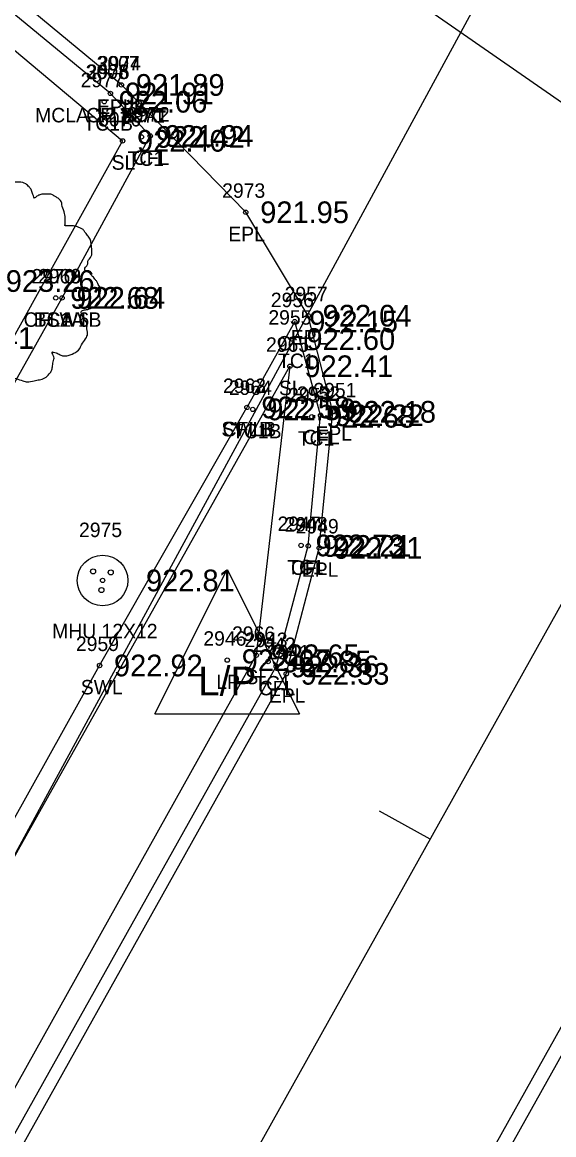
# Model space of a CAD drawing. Extents: x 1575382 to 1578175, y 1099175 to 1101955.
# Drawn here: x 1577037.7 to 1577074.4, y 1100704 to 1100781 of the extents above; entities that cross this region are included whole.
import ezdxf

# ---------------------------------------------------------------- set-up
doc = ezdxf.new("R2010")
doc.units = 0
for name, color, linetype in [('RD_EX_Conc', 7, 'Continuous'), ('RD_EX_Conc_txCode', 7, 'Continuous'), ('RD_EX_DR_Inlet', 7, 'Continuous'), ('RD_EX_Road', 7, 'Continuous'), ('RD_EX_Road_txCode', 7, 'Continuous'), ('RD_EX_TX_Conc_ELEV', 7, 'Continuous'), ('RD_EX_TX_Road_ELEV', 7, 'Continuous'), ('RD_EX_TX_UT_ELEV', 7, 'Continuous'), ('RD_EX_TX_VEG_ELEV', 7, 'Continuous'), ('RD_EX_UT', 7, 'Continuous'), ('RD_EX_UT_txCode', 7, 'Continuous'), ('RD_EX_VEG', 7, 'Continuous'), ('RD_EX_VEG_txCode', 7, 'Continuous'), ('RD_HC_Cl', 7, 'Continuous'), ('RD_HC_Data_Tic', 7, 'Continuous'), ('RD_SMD_Locator', 7, 'Continuous')]:
    doc.layers.add(name, color=color, linetype=linetype)

msp = doc.modelspace()

# ---------------------------------------------------------------- linework, layer by layer
at = {"layer": 'RD_EX_Conc'}
msp.add_line((1577028.227, 1100740.206), (1577040.428, 1100761.953), dxfattribs=at)
for points in [[(1577043.777, 1100776.098), (1576999.879, 1100812.296), (1576959.091, 1100842.628), (1576920.948, 1100878.726), (1576886.666, 1100919.361), (1576858.724, 1100961.136), (1576834.43, 1101008.647), (1576816.373, 1101055.231), (1576803.494, 1101104.71), (1576791.52, 1101152.573)], [(1577047.472, 1100660.341), (1577079.611, 1100717.857), (1577079.611, 1100717.857), (1577102.318, 1100758.516), (1577114.185, 1100779.635), (1577126.083, 1100804.335)], [(1577040.428, 1100761.953), (1577046.526, 1100773.156), (1577043.777, 1100776.098)], [(1576915.514, 1100485.425), (1576931.673, 1100514.72), (1576963.555, 1100571.695), (1576980.254, 1100601.726), (1577004.865, 1100645.934), (1577028.803, 1100689.209), (1577055.236, 1100736.453), (1577057.454, 1100744.788), (1577058.3, 1100753.828), (1577056.519, 1100760.313), (1577053.211, 1100754.373)], [(1576891.145, 1100492.999), (1576919.807, 1100523.916), (1576927.444, 1100533.738), (1576954.888, 1100579.32), (1576970.585, 1100607.096), (1576994.857, 1100650.35), (1577020.046, 1100695.255), (1577043.021, 1100736.517), (1577053.211, 1100754.373)]]:
    msp.add_lwpolyline(points, dxfattribs=at)
at = {"layer": 'RD_EX_DR_Inlet'}
for centre, radius in [((1577043.236, 1100742.401), 1.75), ((1577042.572, 1100743.031), 0.175), ((1577043.796, 1100742.961), 0.175), ((1577043.149, 1100741.737), 0.175)]:
    msp.add_circle(centre, radius, dxfattribs=at)
at = {"layer": 'RD_EX_Road'}
for points in [[(1576898.125, 1100449.597), (1576900.298, 1100453.323), (1576908.44, 1100470.191), (1576911.626, 1100476.811), (1576915.143, 1100482.86), (1576932.491, 1100514.031), (1576964.319, 1100571.231), (1576981.085, 1100601.291), (1577005.143, 1100644.548), (1577029.514, 1100688.699), (1577055.929, 1100735.941), (1577058.213, 1100744.654), (1577059.154, 1100754.07), (1577057.45, 1100760.722), (1577053.131, 1100767.877), (1577044.533, 1100776.687), (1577044.533, 1100776.687), (1577000.541, 1100813.123), (1576959.676, 1100843.401), (1576921.642, 1100879.474), (1576887.689, 1100919.798), (1576859.542, 1100961.835), (1576835.397, 1101008.919), (1576817.257, 1101055.711)], [(1576918.426, 1100436.45), (1576919.689, 1100438.104), (1576919.205, 1100438.447), (1576924.616, 1100446.412), (1576935.148, 1100461.397), (1576954.407, 1100495.424), (1576968.796, 1100521.524), (1576985.916, 1100552.3), (1577005.625, 1100587.417), (1577028.135, 1100627.58), (1577046.667, 1100660.868), (1577078.765, 1100718.331)]]:
    msp.add_lwpolyline(points, dxfattribs=at)
at = {"layer": 'RD_EX_UT'}
for p, q in [((1577046.854, 1100733.163), (1577051.854, 1100743.163)), ((1577051.854, 1100743.163), (1577056.854, 1100733.163)), ((1577046.854, 1100733.163), (1577056.854, 1100733.163))]:
    msp.add_line(p, q, dxfattribs=at)
msp.add_lwpolyline([(1576697.982, 1101074.318), (1577079.486, 1100801.524), (1576931.929, 1100529.296), (1577183.503, 1100413.666)], dxfattribs=at)
at = {"layer": 'RD_EX_VEG'}
for points in [[(1576815.034, 1101055.099), (1576833.721, 1101006.581), (1576857.566, 1100960.375), (1576886.692, 1100916.883), (1576920.078, 1100877.681), (1576958.628, 1100841.518), (1576999.237, 1100810.946), (1577044.614, 1100772.82), (1577027.667, 1100742.339), (1577009.85, 1100750.508), (1576988.317, 1100759.291), (1576965.743, 1100773.629), (1576933.976, 1100810.235), (1576917.815, 1100828.049), (1576903.899, 1100864.233), (1576883.403, 1100895.406), (1576864.834, 1100917.249), (1576817.517, 1100956.766)], [(1576914.194, 1100486.819), (1576910.45, 1100488.948), (1576907.96, 1100484.958), (1576892.651, 1100493.173), (1576920.353, 1100523.238), (1576956.046, 1100578.762), (1577056.185, 1100757.222), (1577053.862, 1100737.224), (1576914.194, 1100486.819)]]:
    msp.add_lwpolyline(points, dxfattribs=at)
for points in [[(1577035.673, 1100770.286), (1577035.373, 1100770.311), (1577035.048, 1100770.211), (1577034.799, 1100770.111), (1577034.574, 1100770.036), (1577034.349, 1100769.936), (1577034.049, 1100769.762), (1577033.824, 1100769.562), (1577033.699, 1100769.312), (1577033.649, 1100769.087), (1577033.599, 1100768.812), (1577033.599, 1100768.637), (1577033.474, 1100768.612), (1577033.324, 1100768.637), (1577033.074, 1100768.712), (1577032.824, 1100768.712), (1577032.574, 1100768.712), (1577032.225, 1100768.687), (1577031.875, 1100768.687), (1577031.6, 1100768.637), (1577031.275, 1100768.587), (1577030.9, 1100768.462), (1577030.55, 1100768.337), (1577030.251, 1100768.087), (1577030.001, 1100767.613), (1577029.876, 1100767.263), (1577029.726, 1100767.013), (1577029.876, 1100766.563), (1577030.051, 1100766.213), (1577030.076, 1100766.013), (1577030.151, 1100765.588), (1577030.251, 1100765.364), (1577030.375, 1100765.164), (1577030.301, 1100765.139), (1577029.926, 1100765.089), (1577029.626, 1100764.989), (1577029.201, 1100764.764), (1577028.976, 1100764.539), (1577028.876, 1100764.214), (1577028.851, 1100763.864), (1577028.751, 1100763.664), (1577028.676, 1100763.389), (1577028.651, 1100763.314), (1577028.601, 1100762.99), (1577028.701, 1100762.54), (1577028.726, 1100762.19), (1577028.851, 1100761.965), (1577029.001, 1100761.79), (1577029.176, 1100761.54), (1577029.576, 1100761.315), (1577029.901, 1100761.215), (1577030.101, 1100761.19), (1577029.926, 1100760.691), (1577029.876, 1100760.341), (1577029.751, 1100759.941), (1577029.751, 1100759.866), (1577029.701, 1100759.391), (1577029.851, 1100759.066), (1577029.926, 1100758.691), (1577030.101, 1100758.467), (1577030.375, 1100758.167), (1577030.7, 1100757.942), (1577031.2, 1100757.817), (1577031.6, 1100757.842), (1577032.175, 1100758.017), (1577032.425, 1100758.092), (1577032.4, 1100757.917), (1577032.425, 1100757.542), (1577032.425, 1100757.117), (1577032.574, 1100756.792), (1577032.674, 1100756.517), (1577032.824, 1100756.267), (1577033.149, 1100756.043), (1577033.549, 1100755.968), (1577033.974, 1100755.818), (1577034.424, 1100755.743), (1577034.923, 1100755.718), (1577035.523, 1100755.868), (1577035.798, 1100755.993), (1577035.898, 1100756.168), (1577036.098, 1100756.542), (1577036.048, 1100756.767), (1577036.073, 1100757.367), (1577036.173, 1100757.192), (1577036.348, 1100756.842), (1577036.848, 1100756.542), (1577037.247, 1100756.367), (1577037.722, 1100756.217), (1577038.022, 1100756.143), (1577038.497, 1100756.217), (1577038.872, 1100756.292), (1577039.247, 1100756.417), (1577039.546, 1100756.692), (1577039.721, 1100756.967), (1577039.771, 1100757.242), (1577039.846, 1100757.617), (1577039.896, 1100757.792)], [(1577039.896, 1100757.792), (1577039.821, 1100757.967), (1577039.771, 1100758.217), (1577039.846, 1100758.192), (1577040.021, 1100758.142), (1577040.296, 1100758.017), (1577040.521, 1100757.942), (1577040.846, 1100757.967), (1577041.121, 1100758.067), (1577041.571, 1100758.342), (1577041.845, 1100758.816), (1577042.12, 1100759.216), (1577042.195, 1100759.541), (1577042.145, 1100759.766), (1577042.12, 1100760.266), (1577041.92, 1100760.516), (1577041.87, 1100760.641), (1577041.77, 1100761.04), (1577041.845, 1100761.09), (1577042.12, 1100761.14), (1577042.495, 1100761.265), (1577042.77, 1100761.39), (1577042.995, 1100761.565), (1577043.07, 1100761.79), (1577043.045, 1100762.19), (1577043.095, 1100762.59), (1577043.02, 1100762.74), (1577042.92, 1100762.89), (1577042.845, 1100763.09), (1577042.695, 1100763.239), (1577042.595, 1100763.389), (1577042.495, 1100763.489), (1577042.37, 1100763.639), (1577042.195, 1100763.764), (1577042.045, 1100763.814), (1577041.995, 1100763.964), (1577042.145, 1100764.164), (1577042.195, 1100764.264), (1577042.22, 1100764.489), (1577042.445, 1100764.839), (1577042.495, 1100765.239), (1577042.445, 1100765.663), (1577042.395, 1100765.938), (1577042.245, 1100766.213), (1577042.045, 1100766.463), (1577041.92, 1100766.638), (1577041.745, 1100766.763), (1577041.421, 1100766.888), (1577041.171, 1100766.938), (1577040.821, 1100766.938), (1577040.621, 1100766.988), (1577040.646, 1100767.038), (1577040.646, 1100767.188), (1577040.646, 1100767.463), (1577040.571, 1100767.912), (1577040.421, 1100768.412), (1577040.421, 1100768.437), (1577040.321, 1100768.687), (1577040.096, 1100768.887), (1577039.921, 1100768.987), (1577039.721, 1100769.112), (1577039.471, 1100769.137), (1577039.172, 1100769.137), (1577038.897, 1100769.087), (1577038.697, 1100768.987), (1577038.522, 1100768.862), (1577038.447, 1100769.012), (1577038.347, 1100769.312), (1577038.297, 1100769.462), (1577038.147, 1100769.637), (1577037.922, 1100769.837), (1577037.472, 1100769.961), (1577036.848, 1100769.887), (1577036.548, 1100769.687), (1577036.398, 1100769.512), (1577036.348, 1100769.637), (1577036.148, 1100769.837), (1577036.048, 1100770.011), (1577035.873, 1100770.136), (1577035.723, 1100770.236), (1577035.623, 1100770.286)]]:
    msp.add_spline(points, degree=3, dxfattribs=at)
at = {"layer": 'RD_HC_Cl'}
for p, q in [((1577088.898, 1100765.75), (1577000.647, 1100827.242)), ((1576888.29, 1100406.318), (1577092.181, 1100771.631))]:
    msp.add_line(p, q, dxfattribs=at)
at = {"layer": 'RD_HC_Data_Tic'}
msp.add_line((1577065.875, 1100724.498), (1577062.382, 1100726.447), dxfattribs=at)
at = {"layer": 'RD_SMD_Locator'}
for centre in [(1577044.533, 1100776.687), (1577044.533, 1100776.687), (1577043.777, 1100776.098), (1577043.777, 1100776.098), (1577043.346, 1100775.524), (1577044.614, 1100772.82), (1577045.919, 1100773.087), (1577046.526, 1100773.156), (1577053.131, 1100767.877), (1577039.993, 1100761.951), (1577040.428, 1100761.953), (1577040.428, 1100761.953), (1577056.519, 1100760.313), (1577057.45, 1100760.722), (1577056.326, 1100759.101), (1577056.185, 1100757.222), (1577053.211, 1100754.373), (1577053.211, 1100754.373), (1577053.618, 1100754.236), (1577057.693, 1100753.727), (1577058.3, 1100753.828), (1577059.154, 1100754.07), (1577056.959, 1100744.823), (1577057.454, 1100744.788), (1577058.213, 1100744.654), (1577043.236, 1100742.401), (1577053.862, 1100737.224), (1577043.021, 1100736.517), (1577051.854, 1100736.887), (1577054.675, 1100736.79), (1577055.236, 1100736.453), (1577055.929, 1100735.941)]:
    msp.add_circle(centre, 0.15, dxfattribs=at)

# ---------------------------------------------------------------- texts
at = {"layer": 'RD_EX_Conc_txCode'}
for s, p in [('3008', (1577042.069, 1100777.098)), ('2976', (1577042.124, 1100777.098)), ('2977', (1577041.716, 1100776.524)), ('MCLA 12 FLAT', (1577038.573, 1100774.098)), ('CFLB', (1577042.1, 1100774.098)), ('2971', (1577044.572, 1100774.087)), ('2972', (1577044.896, 1100774.156)), ('TC1B', (1577041.913, 1100773.524)), ('TC1', (1577044.958, 1100771.087)), ('CFL', (1577045.321, 1100771.156)), ('2970', (1577038.323, 1100762.951)), ('2968', (1577038.774, 1100762.953)), ('2969', (1577038.774, 1100762.953)), ('2956', (1577054.865, 1100761.313)), ('CFLA 6', (1577037.774, 1100759.953)), ('TC1A', (1577038.544, 1100759.951)), ('BSW1B', (1577038.475, 1100759.953)), ('2955', (1577054.696, 1100760.101)), ('CFL', (1577055.314, 1100758.313)), ('TC1', (1577055.365, 1100757.101)), ('2962', (1577051.557, 1100755.373)), ('2963', (1577051.557, 1100755.373)), ('2964', (1577051.964, 1100755.236)), ('2952', (1577056.67, 1100754.828)), ('2953', (1577056.063, 1100754.727)), ('SWLB', (1577051.447, 1100752.373)), ('CFLB', (1577051.533, 1100752.373)), ('TC1B', (1577052.185, 1100752.236)), ('TC1', (1577056.732, 1100751.727)), ('CFL', (1577057.095, 1100751.828)), ('2947', (1577055.329, 1100745.823)), ('2948', (1577055.824, 1100745.788)), ('TC1', (1577055.998, 1100742.823)), ('CFL', (1577056.249, 1100742.788)), ('2959', (1577041.391, 1100737.517)), ('2943', (1577053.045, 1100737.79)), ('2942', (1577053.606, 1100737.453)), ('TC1', (1577053.715, 1100734.79)), ('SWL', (1577041.73, 1100734.517)), ('CFL', (1577054.031, 1100734.453))]:
    msp.add_text(s, height=1, dxfattribs=at).set_placement(p)
at = {"layer": 'RD_EX_Road_txCode'}
for s, p in [('3007', (1577042.825, 1100777.687)), ('2974', (1577042.903, 1100777.687)), ('EPLA', (1577042.84, 1100774.687)), ('EPLB', (1577042.856, 1100774.687)), ('2973', (1577051.501, 1100768.877)), ('EPL', (1577051.927, 1100765.877)), ('2957', (1577055.82, 1100761.722)), ('EPL', (1577056.245, 1100758.722)), ('2951', (1577057.808, 1100755.07)), ('EPL', (1577057.949, 1100752.07)), ('2949', (1577056.583, 1100745.654)), ('EPL', (1577057.008, 1100742.654)), ('2941', (1577054.582, 1100736.941)), ('EPL', (1577054.724, 1100733.941))]:
    msp.add_text(s, height=1, dxfattribs=at).set_placement(p)
at = {"layer": 'RD_EX_TX_Conc_ELEV'}
for s, p in [('921.91', (1577044.777, 1100775.348)), ('921.91', (1577044.777, 1100775.348)), ('922.06', (1577044.346, 1100774.774)), ('922.42', (1577046.919, 1100772.337)), ('921.94', (1577047.526, 1100772.406)), ('922.68', (1577040.993, 1100761.201)), ('922.64', (1577041.428, 1100761.203)), ('922.64', (1577041.428, 1100761.203)), ('922.15', (1577057.519, 1100759.563)), ('922.60', (1577057.326, 1100758.351)), ('922.58', (1577054.211, 1100753.623)), ('922.58', (1577054.211, 1100753.623)), ('922.59', (1577054.618, 1100753.486)), ('922.68', (1577058.693, 1100752.977)), ('922.22', (1577059.3, 1100753.078)), ('922.73', (1577057.959, 1100744.073)), ('922.21', (1577058.454, 1100744.038)), ('922.85', (1577055.675, 1100736.04)), ('922.92', (1577044.021, 1100735.767)), ('922.36', (1577056.236, 1100735.703))]:
    msp.add_text(s, height=1.5, dxfattribs=at).set_placement(p)
at = {"layer": 'RD_EX_TX_Road_ELEV'}
for s, p in [('921.89', (1577045.533, 1100775.937)), ('921.89', (1577045.533, 1100775.937)), ('921.95', (1577054.131, 1100767.127)), ('922.04', (1577058.45, 1100759.972)), ('922.18', (1577060.154, 1100753.32)), ('922.21', (1577059.213, 1100743.904)), ('922.33', (1577056.929, 1100735.191))]:
    msp.add_text(s, height=1.5, dxfattribs=at).set_placement(p)
at = {"layer": 'RD_EX_TX_UT_ELEV'}
for s, p in [('923.41', (1577032.365, 1100758.427)), ('922.81', (1577046.236, 1100741.651)), ('922.67', (1577052.854, 1100736.137))]:
    msp.add_text(s, height=1.5, dxfattribs=at).set_placement(p)
at = {"layer": 'RD_EX_TX_VEG_ELEV'}
for s, p in [('922.40', (1577045.614, 1100772.07)), ('923.26', (1577036.541, 1100762.369)), ('922.41', (1577057.185, 1100756.472)), ('922.65', (1577054.862, 1100736.474))]:
    msp.add_text(s, height=1.5, dxfattribs=at).set_placement(p)
at = {"layer": 'RD_EX_UT'}
msp.add_text('L/P', height=2, dxfattribs=at).set_placement((1577049.845, 1100734.444))
at = {"layer": 'RD_EX_UT_txCode'}
for s, p in [('2975', (1577041.606, 1100745.401)), ('MHU 12X12', (1577039.748, 1100738.401)), ('2946', (1577050.2, 1100737.887)), ('LP', (1577051.098, 1100734.887))]:
    msp.add_text(s, height=1, dxfattribs=at).set_placement(p)
at = {"layer": 'RD_EX_VEG_txCode'}
for s, p in [('3076', (1577042.921, 1100773.82)), ('SL', (1577043.858, 1100770.82)), ('2965', (1577054.531, 1100758.222)), ('SL', (1577055.429, 1100755.222)), ('2966', (1577052.185, 1100738.224)), ('SL', (1577053.106, 1100735.224))]:
    msp.add_text(s, height=1, dxfattribs=at).set_placement(p)

doc.saveas('drawing.dxf')
